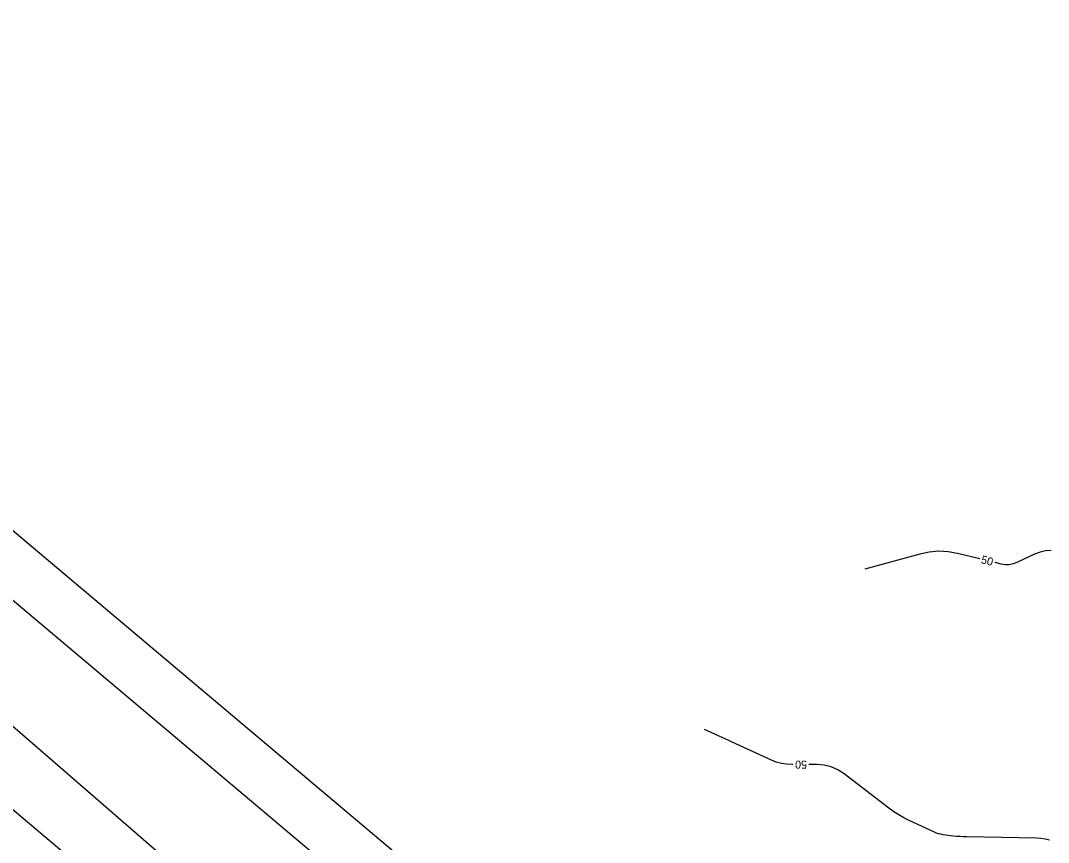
# Model space of a CAD drawing. Extents: x 2384780 to 2405861, y 547869 to 573706.
# Drawn here: x 2391735.9 to 2392121.2, y 553789.9 to 554097.9 of the extents above; entities that cross this region are included whole.
import ezdxf

# ---------------------------------------------------------------- set-up
doc = ezdxf.new("R2010")
doc.units = 0
for name, color, linetype in [('Old_Level_10', 7, 'Continuous'), ('Old_Level_61', 7, 'Continuous'), ('Prop Buffer Zone 1', 7, 'Continuous'), ('Prop Buffer Zone 2', 7, 'Continuous')]:
    doc.layers.add(name, color=color, linetype=linetype)

msp = doc.modelspace()

# ---------------------------------------------------------------- linework, layer by layer
at = {"layer": 'Old_Level_10'}
msp.add_line((2391860.4825, 553722.89325), (2391400.967, 554120.885), dxfattribs=at)
at = {"layer": 'Old_Level_61'}
for points in [[(2392095.4135, 553896.16675), (2392087.046, 553898.194), (2392083.5265, 553898.821), (2392080.01375, 553898.99475), (2392076.50775, 553898.71525), (2392073.00875, 553897.9825), (2392052.29975, 553892.29975)], [(2392122.2295, 553899.2995), (2392120.0925, 553899.15975), (2392118.002, 553898.696), (2392115.9575, 553897.908), (2392109.355, 553894.80475), (2392107.927, 553894.26875), (2392106.473, 553893.99125), (2392104.99275, 553893.972), (2392103.4865, 553894.211), (2392101.245, 553894.754)], [(2392025.2895, 553819.054), (2392024.94725, 553819.054), (2392022.9695, 553819.1585), (2392021.0375, 553819.47225), (2392019.1515, 553819.995), (2392017.311, 553820.72675), (2392002.323, 553827.624), (2392001.1615, 553828.1585), (2392000, 553828.693), (2391998.8385, 553829.2275), (2391997.677, 553829.762), (2391992.2565, 553832.2565)], [(2392121.56875, 553790.71975), (2392119.9505, 553791.08825), (2392118.30725, 553791.32275), (2392116.63925, 553791.42325), (2392090.4265, 553791.9455), (2392089.2175, 553791.9855), (2392088.01075, 553792.05675), (2392086.8065, 553792.15975), (2392085.6045, 553792.2945), (2392081.68125, 553792.7855), (2392080.84975, 553792.92225), (2392080.03625, 553793.12175), (2392079.24075, 553793.38425), (2392078.46325, 553793.70975), (2392068.98225, 553798.113), (2392066.98225, 553799.1085), (2392065.045, 553800.2085), (2392063.171, 553801.41275), (2392061.36, 553802.72125), (2392044.54075, 553815.582), (2392042.197, 553817.101), (2392039.70625, 553818.186), (2392037.0685, 553818.837), (2392034.28375, 553819.054), (2392031.2895, 553819.054)]]:
    msp.add_lwpolyline(points, dxfattribs=at)
at = {"layer": 'Prop Buffer Zone 1'}
for p, q in [((2391883.60825, 553753.75325), (2391434.222, 554132.1035)), ((2391844.10775, 553708.5765), (2391370.7443, 554107.11367))]:
    msp.add_line(p, q, dxfattribs=at)
at = {"layer": 'Prop Buffer Zone 2'}
msp.add_line((2391896.48925, 553769.05275), (2391456.39225, 554139.58225), dxfattribs=at)

# ---------------------------------------------------------------- texts
at = {"layer": 'Old_Level_61'}
for rotation, p in [(346.3811139, (2392095.6805, 553894.55875)), (180, (2392030.6515, 553820.554))]:
    msp.add_text('50', height=3, rotation=rotation, dxfattribs=at).set_placement(p)

doc.saveas('drawing.dxf')
